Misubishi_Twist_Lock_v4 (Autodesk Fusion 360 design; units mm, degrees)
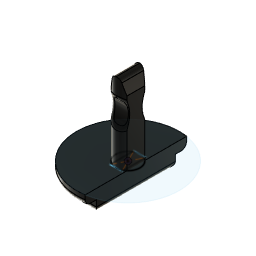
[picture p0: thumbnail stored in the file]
sketch "Sketch1" plane through (0, 0, 0) normal (0, 0, 1) x axis (1, 0, 0)
  line L1 (-2, 10) -> (2, 10)
  line L2 (-2, -10) -> (-2, 10)
  line L3 (2, -10) -> (-2, -10)
  line L4 (2, 10) -> (2, -10)
  line L5 (-2, -10) -> (2, 10)
  line L6 (2, -10) -> (-2, 10)
  circle C1 centre (0, 0) radius 13
  point P1 (0, 0)
  point P2 (0, 0)
  point P7 (0, 0)
  point P5 (-2, -10)
  point P6 (2, -10)
  coincident P1 P2
  horizontal L1
  perpendicular L1 L2
  parallel L1 L3
  parallel L2 L4
  coincident L5 P7
  coincident L6 P7
  coincident P1 P7
  dimension "d1" diameter C1 = 26
  dimension "d34" distance P5 P6 = 4
extrude "Extrude1" new body sketch "Sketch1" profile of C1 L2 L4 along normal blind 2.5
extrude "Extrude2" add sketch "Sketch1" profile of L1 L2 L3 L4 against normal blind 3
fillet "Fillet1" ChordLen 2
sketch "Sketch2" plane through (0, 0, 2.5) normal (0, 0, 1) x axis (-1, 0, 0)
  line L1 (1.5, -3) -> (-1.5, -3)
  line L2 (1.5, 3) -> (1.5, -3)
  line L3 (-1.5, 3) -> (1.5, 3)
  line L4 (-1.5, -3) -> (-1.5, 3)
  line L5 (1.5, 3) -> (-1.5, -3)
  line L6 (-1.5, 3) -> (1.5, -3)
  circle C1 centre (0, 0) radius 13
  circle C2 centre (0, 0) radius 3
  point P1 (0, 0)
  point P3 (0, 0)
  point P8 (0, 0)
  point P6 (1.5, 3)
  point P7 (-1.5, 3)
  coincident P1 P3
  horizontal L1
  perpendicular L1 L2
  parallel L1 L3
  parallel L2 L4
  coincident L5 P8
  coincident L6 P8
  coincident P3 P8
  dimension "d7" diameter C2 = 6
  dimension "d8" distance P6 P7 = 3
extrude "Extrude4" add sketch "Sketch2" profile of C2 L2 L4 along normal blind 20
sketch "Sketch3" plane through (0, 0, 22.5) normal (0, 0, 1) x axis (-1, 0, 0)
  line L1 (-0.9371, -3) -> (0.9371, -3)
  line L2 (-0.9371, 3) -> (-0.9371, -3)
  line L3 (0.9371, 3) -> (-0.9371, 3)
  line L4 (0.9371, -3) -> (0.9371, 3)
  line L5 (-0.9371, 3) -> (0.9371, -3)
  line L6 (0.9371, 3) -> (-0.9371, -3)
  circle C1 centre (0, 0) radius 3
  point P7 (0, 0)
  point P2 (0, 0)
  point P4 (-0.9371, -3)
  point P5 (-0.9371, 3)
  horizontal L1
  perpendicular L1 L2
  parallel L1 L3
  parallel L2 L4
  coincident L5 P7
  coincident L6 P7
  coincident P2 P7
  dimension "d31" distance P4 P5 = 6
extrude "Extrude5" cut sketch "Sketch3" profile of C1 L2 L4 against normal blind 5
draft "Draft1" Angle1 16.4 Angle2 0
fillet "Fillet2" ChordLen 1.5
work_plane "WorkPlane1" RotateAngle 0
sketch "Sketch4" plane through (3, 0, 11.5831) normal (1, 0, 0) x axis (0, 1, 0)
  curve K1 (3, 0) -> (3, 6)
  curve K2 (4.4, 3) -> (1.6, 3)
  line L1 (0, -3) -> (0, 12.5)
  circle C1 centre (0, 3) radius 3
  closed curve K3 centre (3, 3)
  closed curve K4 centre (-3, 3)
  point P1 (0, 0)
  point P3 (3, 3)
  point P4 (3, 6)
  point P5 (3, 0)
  point P6 (1.6, 3)
  point P7 (4.4, 3)
  coincident P1 C1
  coincident C1 P3
  vertical K1
  coincident K3 P4
  coincident K3 P5
  coincident K3 P6
  coincident K3 P7
  vertical L1
  symmetric K3 L1 K4
  dimension "d21" = 2.8
extrude "Extrude6" cut sketch "Sketch4" profile of C1 K3 K4 against normal blind 6.5
fillet "Fillet3" radius 1.25
work_plane "WorkPlane2" RotateAngle 0
sketch "Sketch5" plane through (3, 0, 8.63) normal (1, 0, 0) x axis (0, 1, 0)
  line L1 (-14, 17) -> (14, 17)
  line L2 (-14, -17) -> (-14, 17)
  line L3 (14, -17) -> (-14, -17)
  line L4 (14, 17) -> (14, -17)
  line L5 (-14, -17) -> (14, 17)
  line L6 (14, -17) -> (-14, 17)
  point P6 (0, 0)
  point P1 (0, 0)
  horizontal L1
  perpendicular L1 L2
  parallel L1 L3
  parallel L2 L4
  coincident L5 P6
  coincident L6 P6
  coincident P1 P6
extrude "Extrude7" cut sketch "Sketch5" profile of L1 L2 L3 L4 along normal blind 10 and against normal blind 1
sketch "Sketch6" plane through (-6.9566, 0, 2.0474) normal (-0.9593, 0, 0.2823) x axis (0, -1, 0)
  line L1 (2.7489, 20.3833) -> (-2.7489, 20.3833)
  line L2 (1.7875, 16.1079) -> (-1.7875, 16.1079)
  line L3 (5.7734, 19.6528) -> (-4.708, 19.6528)
  line L4 (5.7734, 14.1994) -> (5.7734, 19.6528)
  line L5 (-4.708, 14.1994) -> (5.7734, 14.1994)
  line L6 (-4.708, 19.6528) -> (-4.708, 14.1994)
  curve K1 (-1.8211, 16.1952) -> (-1.7875, 16.1079)
  curve K2 (1.7875, 16.1079) -> (1.8211, 16.1952)
  closed curve K3 centre (0, 24.6391)
  closed curve K4 centre (0, 24.6391)
  horizontal L3
  vertical L4
  horizontal L5
  vertical L6
extrude "Extrude8" cut sketch "Sketch6" profile of K3 L2 K4 L3 L4 L5 L6 along normal blind 2.5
